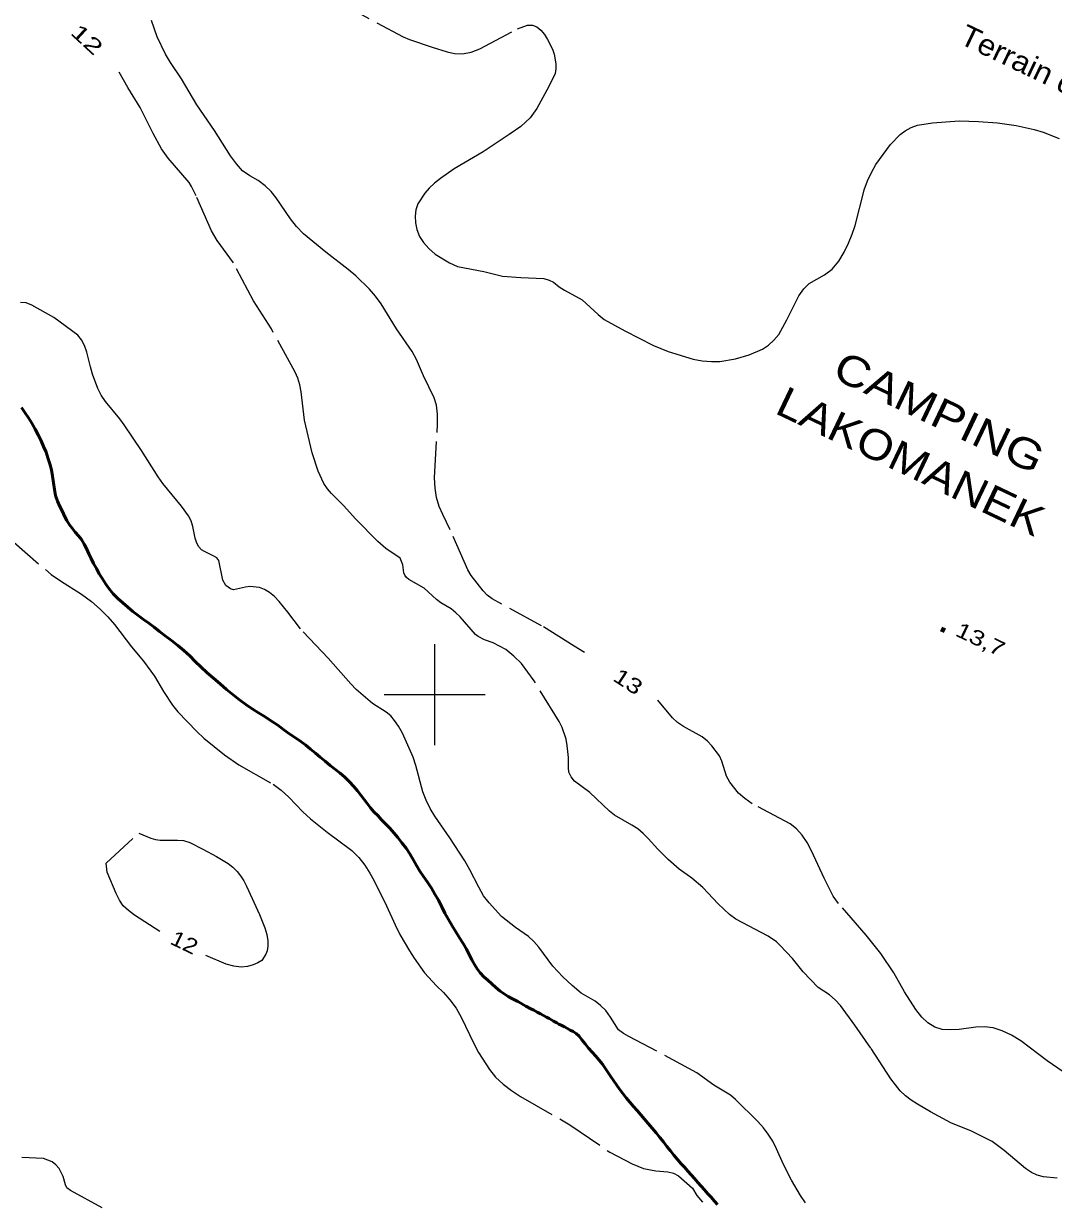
# Model space of a CAD drawing. Extents: x 355726 to 357533, y 5103782 to 5105258.
# Drawn here: x 356159.2 to 356261.4, y 5104649.7 to 5104766.6 of the extents above; entities that cross this region are included whole.
import ezdxf
from ezdxf.enums import TextEntityAlignment as Align

# ---------------------------------------------------------------- set-up
doc = ezdxf.new("R2010")
doc.units = 0
doc.header["$LTSCALE"] = 0.6
for name, pattern in [('DASH_DOUBLE_DOT', [9.2, 5, -1.2, 0.3, -1.2, 0.3, -1.2]), ('LONG_DASH_SHORT_DASH', [9.9, 6, -1.2, 1.5, -1.2]), ('LONG_DASHED', [7.5, 6, -1.5])]:
    doc.linetypes.add(name, pattern=pattern)
for name, color, linetype, lineweight in [('2', 7, 'LONG_DASHED', 13), ('3', 7, 'Continuous', 140), ('4', 7, 'DASH_DOUBLE_DOT', 53), ('56', 7, 'LONG_DASH_SHORT_DASH', 25), ('61', 7, 'Continuous', 13)]:
    doc.layers.add(name, color=color, linetype=linetype, lineweight=lineweight)

msp = doc.modelspace()

# ---------------------------------------------------------------- linework, layer by layer
at = {"layer": '2'}
for points in [[(356190.31, 5104768.8), (356196.86, 5104765.26), (356197.51, 5104764.99), (356199.75, 5104764.22), (356201.23, 5104763.78), (356201.97, 5104763.62), (356202.74, 5104763.57), (356203.62, 5104763.73), (356204.46, 5104764.07), (356208.21, 5104766.04), (356209.22, 5104766.42), (356209.69, 5104766.42), (356210.12, 5104766.24), (356210.53, 5104765.93), (356210.89, 5104765.48), (356211.18, 5104765.01), (356211.68, 5104764.04), (356211.84, 5104763.55), (356212.03, 5104762.57), (356212.02, 5104762.09), (356211.94, 5104761.63), (356211.32, 5104760.34), (356210.12, 5104758.15), (356209.46, 5104757.22), (356208.53, 5104756.38), (356207.39, 5104755.57), (356204.8, 5104753.84), (356201.92, 5104752.16), (356200.57, 5104751.22), (356199.97, 5104750.75), (356199.44, 5104750.26), (356199.01, 5104749.76), (356198.34, 5104748.7), (356198.14, 5104748.09), (356198.06, 5104747.46), (356198.08, 5104746.8), (356198.21, 5104746.13), (356198.48, 5104745.46), (356198.9, 5104744.84), (356199.43, 5104744.25), (356200.06, 5104743.71), (356201.47, 5104742.84), (356202.26, 5104742.49), (356204.88, 5104741.98), (356206.71, 5104741.53), (356208.56, 5104741.37), (356210.83, 5104741.29), (356211.36, 5104741.13), (356211.78, 5104740.92), (356212.35, 5104740.46), (356212.88, 5104740.13), (356214.64, 5104739.18), (356216.21, 5104737.7), (356216.81, 5104737.23), (356218.87, 5104736.09), (356221.72, 5104734.62), (356223.17, 5104734.05), (356225.65, 5104733.28), (356226.55, 5104733.12), (356227.45, 5104733.04), (356228.3, 5104733.05), (356229.83, 5104733.3), (356231.19, 5104733.71), (356232.51, 5104734.28), (356233.12, 5104734.68), (356233.66, 5104735.17), (356234.13, 5104735.74), (356234.93, 5104737.19), (356236.14, 5104739.55), (356236.62, 5104740.26), (356237.16, 5104740.8), (356238.66, 5104741.65), (356239.44, 5104742.22), (356240.1, 5104743), (356240.61, 5104743.88), (356241.06, 5104744.78), (356241.41, 5104745.68), (356241.71, 5104746.55), (356242.62, 5104750.09), (356242.93, 5104750.97), (356243.32, 5104751.79), (356243.76, 5104752.58), (356245.23, 5104754.57), (356246.17, 5104755.58), (356246.69, 5104755.95), (356247.27, 5104756.26), (356247.91, 5104756.49), (356249.38, 5104756.74), (356252.03, 5104756.94), (356253.95, 5104756.87), (356255.83, 5104756.72)], [(356214.85, 5104704.18), (356213.82, 5104704.79), (356210.61, 5104706.84), (356205.69, 5104709.51), (356205.21, 5104709.87), (356204.81, 5104710.29), (356203.61, 5104711.82), (356203.28, 5104712.38), (356201.53, 5104716.36), (356200.79, 5104717.86), (356200.45, 5104718.67), (356200.18, 5104719.54), (356200.03, 5104720.47), (356199.99, 5104721.51), (356200.28, 5104726.84), (356200.28, 5104727.84), (356200.17, 5104728.71), (356199.94, 5104729.46), (356198.88, 5104731.62), (356198.19, 5104733.26), (356197.77, 5104734.05), (356196.2, 5104736.28), (356194.67, 5104738.76), (356194.13, 5104739.53), (356193.52, 5104740.24), (356192.16, 5104741.55), (356191.42, 5104742.19), (356189.21, 5104743.88), (356186.99, 5104745.73), (356186.28, 5104746.43), (356185.69, 5104747.19), (356184.28, 5104749.29), (356183.78, 5104749.9), (356183.19, 5104750.49), (356182.47, 5104751), (356181.67, 5104751.46), (356180.94, 5104751.98), (356180.33, 5104752.66), (356179.74, 5104753.44), (356178.15, 5104755.98), (356176.4, 5104758.51), (356174.86, 5104761.09), (356173.77, 5104762.71), (356173.28, 5104763.55), (356172.47, 5104765.26), (356171.9, 5104766.88)], [(356202.54, 5104707.72), (356202.1, 5104708.12), (356201.63, 5104708.5), (356200.61, 5104709.09), (356200.16, 5104709.42), (356198.94, 5104710.55), (356197.44, 5104711.41), (356197.2, 5104711.61), (356197.04, 5104711.84), (356196.94, 5104712.09), (356196.82, 5104712.88), (356196.57, 5104713.55), (356195.14, 5104714.51), (356194.35, 5104715.2), (356192.16, 5104717.41), (356190.95, 5104718.75), (356189.76, 5104719.95), (356189.35, 5104720.41), (356188.99, 5104720.94), (356188.45, 5104722.16), (356187.84, 5104723.98), (356187.08, 5104727.23), (356186.76, 5104730.04), (356186.61, 5104730.75), (356186.41, 5104731.41), (356186.16, 5104731.99), (356183.79, 5104736.28), (356182.01, 5104739.07), (356180.02, 5104742.84), (356178.43, 5104745.04), (356177.84, 5104746.01), (356176.34, 5104749.48), (356175.88, 5104750.41), (356175.63, 5104750.8), (356173.56, 5104753.21), (356172.9, 5104754.15), (356172.05, 5104755.67), (356170.77, 5104758.26), (356169.55, 5104760.22), (356168.69, 5104761.75)], [(356255.83, 5104756.72), (356257.68, 5104756.46), (356259.49, 5104756.05), (356260.36, 5104755.79), (356261.94, 5104755.18)], [(356210.33, 5104674.94), (356209.83, 5104675.51), (356209.3, 5104676.01), (356208.02, 5104676.88), (356206.64, 5104677.99), (356205.4, 5104679.33), (356204.85, 5104680.05), (356204.36, 5104680.88), (356203.48, 5104682.63), (356202.98, 5104683.5), (356201.5, 5104685.8), (356200.02, 5104687.93), (356199.56, 5104688.69), (356199.15, 5104689.53), (356198.82, 5104690.36), (356198.13, 5104692.97), (356197.87, 5104693.79), (356196.81, 5104696.19), (356196.42, 5104696.87), (356196.02, 5104697.44), (356195.63, 5104697.88), (356195.19, 5104698.25), (356193.81, 5104699.11), (356192.22, 5104700.51), (356191.67, 5104701.07), (356189.44, 5104703.61), (356186.69, 5104706.51), (356185.43, 5104708.17), (356184.55, 5104709.24), (356184.1, 5104709.72), (356183.6, 5104710.13), (356183.1, 5104710.42), (356182.63, 5104710.62), (356181.67, 5104710.71), (356181.22, 5104710.66), (356180.03, 5104710.41), (356179.74, 5104710.48), (356179.28, 5104710.84), (356178.99, 5104711.34), (356178.57, 5104713.3), (356178.39, 5104713.57), (356178.1, 5104713.75), (356177.15, 5104714.19), (356176.86, 5104714.38), (356176.59, 5104714.67), (356176.39, 5104715.03), (356176.23, 5104715.53), (356176, 5104716.69), (356175.82, 5104717.23), (356175.58, 5104717.75), (356174.89, 5104718.71), (356173.01, 5104720.96), (356172.57, 5104721.59), (356170.92, 5104724.23), (356169.19, 5104726.75), (356168.75, 5104727.37), (356167.33, 5104729.07), (356166.91, 5104729.7), (356166.58, 5104730.38), (356166.06, 5104731.8), (356165.84, 5104732.51), (356165.48, 5104733.99), (356165.26, 5104734.65), (356164.96, 5104735.19), (356164.59, 5104735.65), (356162.2, 5104737.42), (356160.01, 5104738.65), (356159.46, 5104738.86), (356158.9, 5104738.91)], [(356157.97, 5104715.34), (356161.94, 5104711.92), (356162.86, 5104711.28), (356164.95, 5104709.96), (356165.95, 5104709.24), (356166.82, 5104708.48), (356167.58, 5104707.71), (356168.22, 5104706.97), (356169.93, 5104704.75), (356171.1, 5104703.32), (356172.21, 5104701.84), (356173.1, 5104700.3), (356173.99, 5104698.94), (356174.51, 5104698.3), (356176.39, 5104696.34), (356177.08, 5104695.69), (356179.14, 5104694.01), (356180.58, 5104693.03), (356183.96, 5104691.12), (356184.78, 5104690.53), (356185.53, 5104689.84)], [(356261.75, 5104652.03), (356260.41, 5104652.17), (356259.78, 5104652.33), (356259.2, 5104652.59), (356258.62, 5104652.97), (356256.5, 5104654.76), (356255.3, 5104655.65), (356253.26, 5104656.7), (356251.21, 5104657.51), (356249.2, 5104658.61), (356247.9, 5104659.38), (356247.26, 5104659.78), (356246.71, 5104660.2), (356246.18, 5104660.7), (356245.24, 5104661.88), (356243.28, 5104664.92), (356241.69, 5104667.21), (356240.26, 5104669.15), (356239.74, 5104669.72), (356239.17, 5104670.22), (356238.05, 5104670.95), (356236.56, 5104672.51), (356235.5, 5104673.83), (356234.29, 5104675.11), (356233.9, 5104675.46), (356233.07, 5104676.05), (356229.87, 5104677.73), (356229.25, 5104678.17), (356228.12, 5104679.25), (356226.61, 5104680.87), (356225.5, 5104681.8), (356224.26, 5104682.68), (356223.15, 5104683.63), (356222.12, 5104684.68), (356221.19, 5104685.74), (356220.68, 5104686.22), (356220.14, 5104686.67), (356219.56, 5104687.05), (356217.83, 5104688.05), (356217.34, 5104688.45), (356215.39, 5104690.3), (356213.88, 5104691.42), (356213.53, 5104691.84), (356213.3, 5104692.29), (356213.26, 5104692.73), (356213.28, 5104693.76), (356213.15, 5104694.96), (356213.03, 5104695.58), (356212.64, 5104696.73), (356212.36, 5104697.32), (356209.87, 5104701.38), (356208.6, 5104703.08), (356207.85, 5104703.83), (356207.05, 5104704.49), (356205.8, 5104705.15), (356204.93, 5104705.42), (356204.32, 5104705.76), (356204.05, 5104705.97), (356202.54, 5104707.72)], [(356258.16, 5104665.65), (356257.24, 5104666.2), (356256.31, 5104666.65), (356255.4, 5104666.94), (356254.54, 5104667.05), (356253.7, 5104667), (356252.04, 5104666.76), (356251.19, 5104666.73), (356250.36, 5104666.78), (356249.63, 5104666.99), (356248.94, 5104667.42), (356248.32, 5104668.01), (356247.73, 5104668.76), (356246.6, 5104670.5), (356245.54, 5104672.41), (356244.27, 5104674.3), (356242.81, 5104676.12), (356240.07, 5104679.26), (356239.54, 5104680.01), (356238.64, 5104681.78), (356237.38, 5104684.49), (356236.94, 5104685.32), (356236.45, 5104686.05), (356235.9, 5104686.69), (356235.26, 5104687.17), (356231.5, 5104689.17), (356230.76, 5104689.68), (356230.15, 5104690.22), (356229.29, 5104691.32), (356228.95, 5104691.9), (356228.49, 5104693.41), (356228.25, 5104693.91), (356227.51, 5104694.92), (356227.06, 5104695.38), (356226.54, 5104695.8), (356224.68, 5104696.84), (356224.09, 5104697.23), (356223.59, 5104697.68), (356222.14, 5104699.44)], [(356185.53, 5104689.84), (356186.93, 5104688.38), (356187.68, 5104687.69), (356189.33, 5104686.36), (356191.78, 5104684.54), (356192.46, 5104683.84), (356193.06, 5104683.09), (356193.56, 5104682.3), (356193.99, 5104681.51), (356195.22, 5104679.05), (356196.07, 5104677.15), (356196.54, 5104676.21), (356197.49, 5104674.58), (356197.96, 5104673.84), (356199, 5104672.41), (356200.19, 5104671.11), (356200.87, 5104670.46), (356201.5, 5104669.72), (356202.12, 5104668.88), (356202.64, 5104668.01), (356203.88, 5104665.37), (356204.34, 5104664.49), (356205.42, 5104662.8), (356206.04, 5104662.05), (356206.79, 5104661.36), (356207.62, 5104660.72), (356208.5, 5104660.13), (356213.4, 5104657.33), (356217.39, 5104654.59), (356219.58, 5104653.44), (356220.71, 5104652.98), (356221.94, 5104652.75), (356223.14, 5104652.66), (356223.7, 5104652.51), (356224.19, 5104652.26), (356225.59, 5104651.04), (356226, 5104650.29), (356226.56, 5104649.65)], [(356172.74, 5104676.51), (356170.22, 5104678.12), (356169.61, 5104678.57), (356169.1, 5104679.05), (356168.71, 5104679.62), (356168.39, 5104680.26), (356167.49, 5104682.37), (356167.4, 5104683.29), (356170.63, 5104686.26), (356171.84, 5104685.76), (356172.28, 5104685.63), (356172.77, 5104685.55), (356174.47, 5104685.57), (356175.08, 5104685.51), (356175.69, 5104685.33), (356176.98, 5104684.67), (356178.34, 5104683.94), (356179.5, 5104683.24), (356179.98, 5104682.88), (356180.4, 5104682.46), (356180.74, 5104682.03), (356181.06, 5104681.53), (356181.32, 5104681.01), (356182.6, 5104678.2), (356183.13, 5104676.87), (356183.33, 5104676.2), (356183.43, 5104675.57), (356183.43, 5104675.03), (356183.36, 5104674.59), (356183.24, 5104674.25), (356182.83, 5104673.62), (356182.46, 5104673.38), (356182, 5104673.18), (356181.44, 5104673.01), (356180.79, 5104672.96), (356180.06, 5104673.05), (356179.32, 5104673.25), (356177.28, 5104674.11)], [(356236.79, 5104649.59), (356236.29, 5104650.3), (356235.4, 5104651.84), (356234.62, 5104653.38), (356233.91, 5104654.95), (356233.53, 5104655.68), (356233.09, 5104656.38), (356232.61, 5104657.03), (356232.06, 5104657.65), (356229.85, 5104659.82), (356229.33, 5104660.26), (356227.68, 5104661.24), (356225.99, 5104662.49), (356219.27, 5104666.08), (356218.73, 5104666.38), (356218.24, 5104666.74), (356217.44, 5104668.01), (356216.97, 5104668.65), (356216.44, 5104669.17), (356215.92, 5104669.58), (356214.53, 5104670.38), (356213.64, 5104671.13), (356212.7, 5104672.01), (356211.71, 5104673.07), (356210.33, 5104674.94)], [(356262.35, 5104662.59), (356260.77, 5104663.68), (356258.16, 5104665.65)], [(356167.01, 5104649.09), (356163.86, 5104650.79), (356163.51, 5104651.05), (356163.35, 5104651.36), (356163.14, 5104652.2), (356162.73, 5104652.99), (356162.41, 5104653.36), (356162.03, 5104653.66), (356161.17, 5104653.98), (356159.04, 5104654.08)]]:
    msp.add_lwpolyline(points, dxfattribs=at)
at = {"layer": '3'}
msp.add_line((356250.25, 5104706.53), (356250.61, 5104706.36), dxfattribs=at)
at = {"layer": '4'}
for points in [[(356159, 5104728.49), (356159.34, 5104728), (356159.69, 5104727.47), (356160.04, 5104726.92)], [(356160.04, 5104726.92), (356160.35, 5104726.32), (356160.65, 5104725.76), (356160.94, 5104725.19), (356161.2, 5104724.63), (356161.44, 5104724.07), (356161.63, 5104723.49), (356161.81, 5104722.88), (356161.98, 5104722.29), (356162.09, 5104721.66), (356162.19, 5104721.01), (356162.29, 5104720.36), (356162.39, 5104719.76), (356162.56, 5104719.18), (356162.8, 5104718.65), (356163.06, 5104718.16), (356163.28, 5104717.69), (356163.5, 5104717.26), (356163.75, 5104716.86), (356164.03, 5104716.51), (356164.34, 5104716.13), (356164.66, 5104715.76), (356164.96, 5104715.38), (356165.21, 5104714.94), (356165.45, 5104714.48), (356165.68, 5104713.98), (356165.91, 5104713.49), (356166.15, 5104713), (356166.43, 5104712.51), (356166.71, 5104711.99), (356167.03, 5104711.48), (356167.37, 5104710.97), (356167.7, 5104710.48), (356168.11, 5104709.99), (356168.56, 5104709.53), (356169.04, 5104709.09), (356169.54, 5104708.68), (356170.05, 5104708.26), (356170.58, 5104707.84), (356171.11, 5104707.45), (356171.65, 5104707.08), (356172.16, 5104706.69), (356172.7, 5104706.26), (356173.25, 5104705.84), (356173.88, 5104705.38), (356174.5, 5104704.88), (356175.11, 5104704.38), (356175.69, 5104703.84), (356176.23, 5104703.3), (356176.81, 5104702.74), (356177.43, 5104702.17), (356178.05, 5104701.62), (356178.71, 5104701.07), (356179.35, 5104700.51), (356179.99, 5104699.98), (356180.62, 5104699.48), (356181.25, 5104699.03), (356181.88, 5104698.59), (356182.53, 5104698.2), (356183.17, 5104697.8), (356183.79, 5104697.38), (356184.43, 5104696.96), (356185.04, 5104696.51), (356185.63, 5104696.09), (356186.2, 5104695.71), (356186.72, 5104695.34), (356187.21, 5104694.97), (356187.69, 5104694.59), (356188.16, 5104694.19), (356188.64, 5104693.8), (356189.12, 5104693.4), (356189.62, 5104692.98), (356190.63, 5104692.2), (356191.08, 5104691.8), (356191.53, 5104691.36), (356191.94, 5104690.92), (356192.33, 5104690.46), (356192.67, 5104690.01), (356193.01, 5104689.58), (356193.32, 5104689.17), (356193.64, 5104688.78), (356193.97, 5104688.38), (356194.34, 5104687.99), (356194.73, 5104687.58), (356195.13, 5104687.18), (356195.53, 5104686.76), (356195.93, 5104686.3), (356196.34, 5104685.82), (356196.75, 5104685.3), (356197.16, 5104684.75), (356197.53, 5104684.19), (356197.88, 5104683.59), (356198.2, 5104683.05), (356198.52, 5104682.5), (356198.89, 5104681.94), (356199.28, 5104681.38), (356199.67, 5104680.8), (356200.02, 5104680.21), (356200.36, 5104679.61), (356200.7, 5104678.96), (356201, 5104678.32)], [(356201, 5104678.32), (356201.36, 5104677.68), (356201.73, 5104677.05), (356202.1, 5104676.47), (356202.47, 5104675.87), (356202.83, 5104675.3), (356203.15, 5104674.73), (356203.43, 5104674.2), (356203.68, 5104673.7), (356203.93, 5104673.22), (356204.21, 5104672.8), (356204.52, 5104672.4), (356204.87, 5104672.01), (356205.26, 5104671.66), (356205.65, 5104671.29), (356206.07, 5104670.93), (356206.49, 5104670.59), (356206.89, 5104670.3), (356207.28, 5104670.05), (356207.66, 5104669.86), (356207.98, 5104669.68), (356208.23, 5104669.54), (356208.56, 5104669.38), (356208.8, 5104669.22), (356209.04, 5104669.09), (356209.52, 5104668.84), (356209.83, 5104668.68), (356210.15, 5104668.5), (356210.48, 5104668.32), (356210.79, 5104668.15), (356211.09, 5104668.01), (356211.35, 5104667.87), (356211.58, 5104667.75), (356211.8, 5104667.61), (356212.11, 5104667.44), (356212.33, 5104667.32), (356212.61, 5104667.17), (356212.86, 5104667.04), (356213.16, 5104666.88), (356213.45, 5104666.72), (356213.73, 5104666.57), (356214.03, 5104666.38), (356214.32, 5104666.11), (356214.61, 5104665.75), (356214.92, 5104665.34), (356215.27, 5104664.93), (356215.63, 5104664.51), (356215.99, 5104664.12), (356216.32, 5104663.72), (356216.63, 5104663.33), (356216.9, 5104662.93), (356217.18, 5104662.53), (356217.45, 5104662.13), (356217.73, 5104661.72), (356218.03, 5104661.29), (356218.33, 5104660.86), (356218.66, 5104660.43), (356218.99, 5104660), (356219.36, 5104659.57), (356219.72, 5104659.13), (356220.08, 5104658.73), (356220.45, 5104658.3), (356220.81, 5104657.88), (356221.19, 5104657.44), (356221.58, 5104656.98), (356221.97, 5104656.51), (356222.33, 5104656.07), (356222.69, 5104655.62), (356223.03, 5104655.18), (356223.38, 5104654.74), (356223.73, 5104654.3), (356224.1, 5104653.88), (356224.45, 5104653.46), (356224.8, 5104653.07), (356225.12, 5104652.72), (356225.43, 5104652.36), (356225.76, 5104651.98), (356226.09, 5104651.59), (356226.44, 5104651.22), (356226.77, 5104650.86), (356227.08, 5104650.5), (356227.42, 5104650.15), (356227.74, 5104649.76), (356228.07, 5104649.42)]]:
    msp.add_lwpolyline(points, dxfattribs=at)
at = {"layer": '61'}
for p, q in [((356200, 5104695), (356200, 5104705)), ((356195, 5104700), (356205, 5104700))]:
    msp.add_line(p, q, dxfattribs=at)

# ---------------------------------------------------------------- texts
at = {"layer": '2'}
for s, rotation, width, p in [('12', 317.317, 1.5, (356164.99, 5104764.45)), ('13', 326.824, 1.3, (356218.78, 5104700.67)), ('12', 334.379, 1.2, (356174.84, 5104674.74))]:
    msp.add_text(s, height=1.5, rotation=rotation, dxfattribs=dict(at, width=width)).set_placement(p, align=Align.CENTER)
at = {"layer": '3', "width": 1.3}
msp.add_text('13,7   ', height=1.5, rotation=334.423, dxfattribs=at).set_placement((356251.54, 5104705.9))
at = {"layer": '56'}
for s, height, rotation, width, p in [('Terrain de camping', 2.1, 334.42, 1.1, (356251.91, 5104764.67)), ('CAMPING  ', 3, 334.532, 1.2, (356239.29, 5104731.48)), ('LAKOMANEK', 3, 334.532, 1.15, (356233.62, 5104727.97))]:
    msp.add_text(s, height=height, rotation=rotation, dxfattribs=dict(at, width=width)).set_placement(p)

doc.saveas('drawing.dxf')
